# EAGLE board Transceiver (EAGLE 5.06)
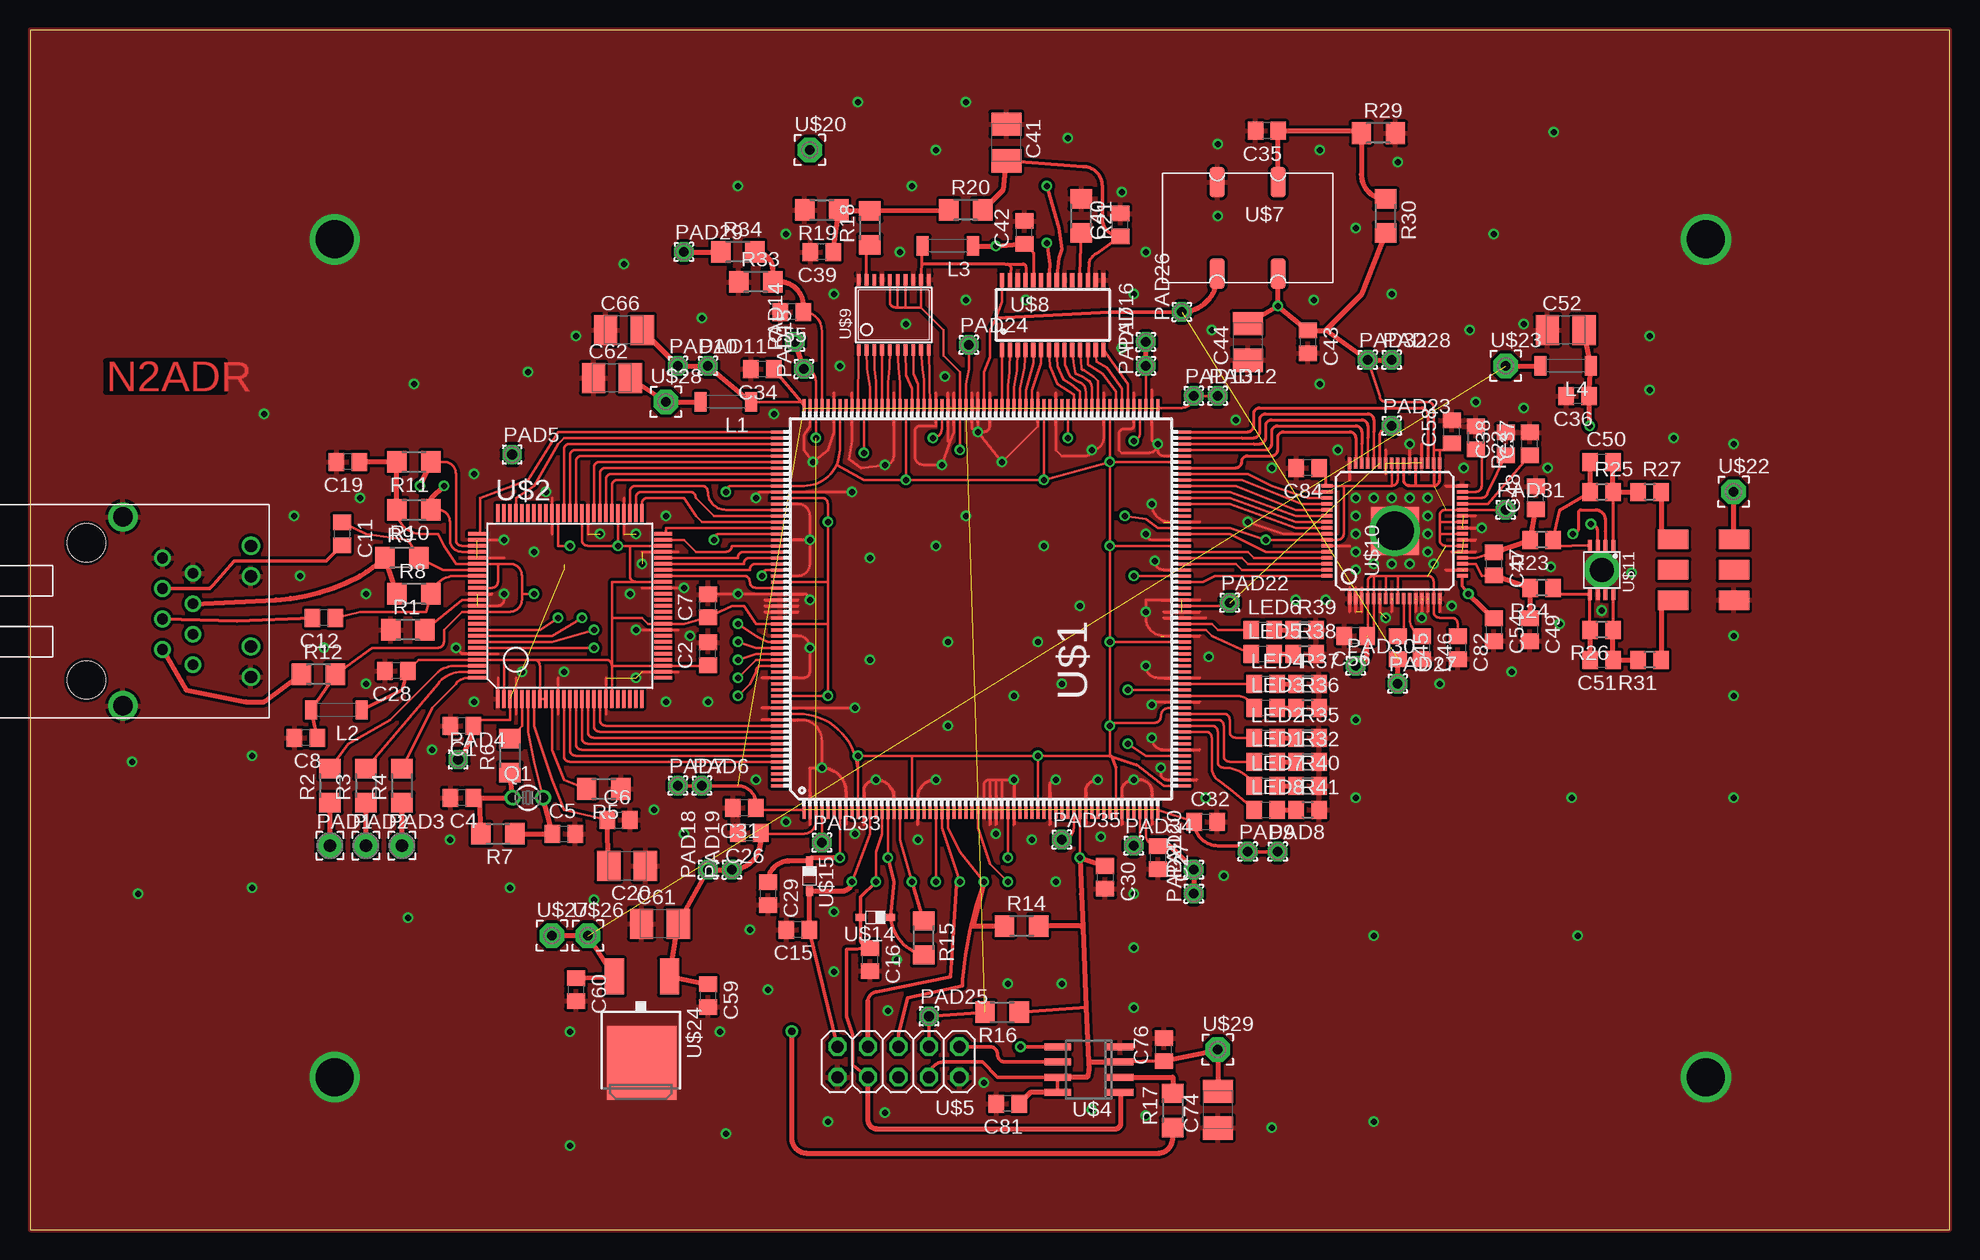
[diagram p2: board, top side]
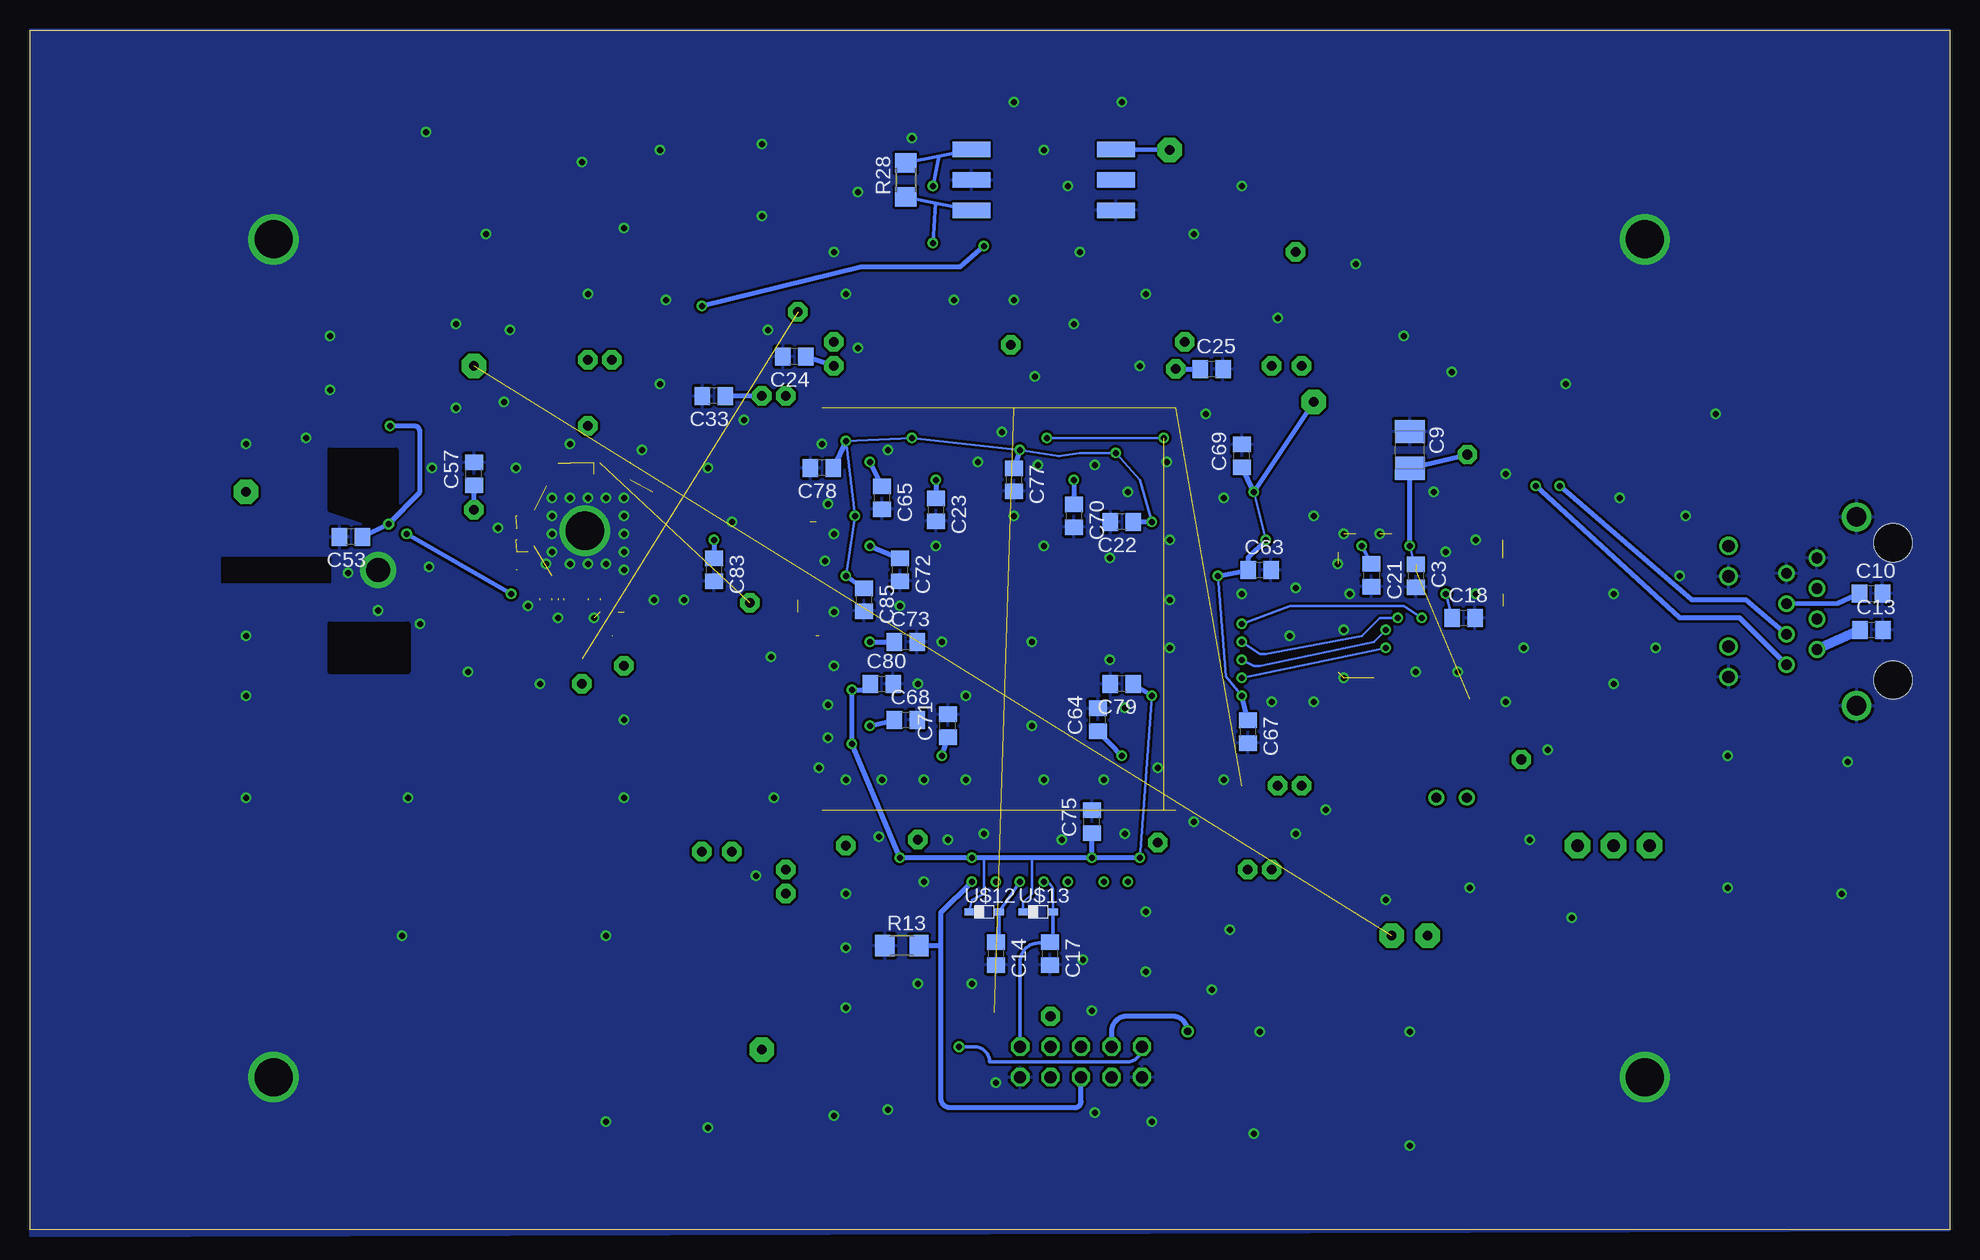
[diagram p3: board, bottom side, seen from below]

Size 160 x 100 mm. Coordinates in mm from the lower left corner, seen from the top.
Outline: 0,0 160,0 160,100 0,100 0,0
Copper layers (1*16): Top 0.035mm / dielectric 1.5mm / Bottom 0.035mm
Design rules "4pcb *": minimum track width 8mil, minimum drill 14mil, track to track 8mil, track to pad 8mil, pad to pad 6mil, via to via 8mil, smd to smd 0mil, copper to edge 0mil, drill to drill 8mil, minimum pad ring 10mil, minimum via ring 8mil, stop-mask expansion 4mil, vias tented up to drill 0mil, thermal gap 10mil
bRestrict: area 128.5,46.5 to 135,50.5; area 129.5,59 to 135,65; area 135,54 to 144,56

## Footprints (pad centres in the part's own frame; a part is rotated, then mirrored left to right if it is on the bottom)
MINI-CD637 = smd 1.651 x 2.54: P$1 -2.54,-2.54; P$2 0,-2.54; P$3 2.54,-2.54; P$4 2.54,2.54; P$5 0,2.54; P$6 -2.54,2.54
C0805 = smd 1.3 x 1.5: 1 -0.95,0; 2 0.95,0
B/3528-21R = smd 1.95 x 2.5: + 1.525,0; - -1.525,0
L4516C = smd 1 x 1.6: 1 -2.1,0; 2 2.1,0
2,15/1,0 = drill 1.016 pad 2.159 octagon: 1 0,0
1,6/0,8 = drill 0.813 pad 1.6 octagon: 1 0,0
TC26V = drill 0.813 round: 1 -1.27,0; 2 1.27,0
R1206 = smd 1.6 x 1.803: 1 -1.422,0; 2 1.422,0
R0805 = smd 1.3 x 1.5: 1 -0.95,0; 2 0.95,0
MINI-KK81 = smd 1.27 x 3.175: P$1 -2.54,6.032; P$2 0,6.032; P$3 2.54,6.032; P$4 2.54,-6.032; P$5 0,-6.032; P$6 -2.54,-6.032
PQFP240 = smd 1.5 x 0.25: 1 -16.75,14.75; 2 -16.75,14.25; 3 -16.75,13.75; 4 -16.75,13.25; 5 -16.75,12.75; 6 -16.75,12.25; 7 -16.75,11.75; 8 -16.75,11.25; 9 -16.75,10.75; 10 -16.75,10.25; 11 -16.75,9.75; 12 -16.75,9.25; 13 -16.75,8.75; 14 -16.75,8.25; 15 -16.75,7.75; 16 -16.75,7.25; 17 -16.75,6.75; 18 -16.75,6.25; 19 -16.75,5.75; 20 -16.75,5.25; 21 -16.75,4.75; 22 -16.75,4.25; 23 -16.75,3.75; 24 -16.75,3.25; 25 -16.75,2.75; 26 -16.75,2.25; 27 -16.75,1.75; 28 -16.75,1.25; 29 -16.75,0.75; 30 -16.75,0.25; 31 -16.75,-0.25; 32 -16.75,-0.75; 33 -16.75,-1.25; 34 -16.75,-1.75; 35 -16.75,-2.25; 36 -16.75,-2.75; 37 -16.75,-3.25; 38 -16.75,-3.75; 39 -16.75,-4.25; 40 -16.75,-4.75; 41 -16.75,-5.25; 42 -16.75,-5.75; 43 -16.75,-6.25; 44 -16.75,-6.75; 45 -16.75,-7.25; 46 -16.75,-7.75; 47 -16.75,-8.25; 48 -16.75,-8.75; 49 -16.75,-9.25; 50 -16.75,-9.75; 51 -16.75,-10.25; 52 -16.75,-10.75; 53 -16.75,-11.25; 54 -16.75,-11.75; 55 -16.75,-12.25; 56 -16.75,-12.75; 57 -16.75,-13.25; 58 -16.75,-13.75; 59 -16.75,-14.25; 60 -16.75,-14.75; 121 16.75,-14.75; 122 16.75,-14.25; 123 16.75,-13.75; 124 16.75,-13.25; 125 16.75,-12.75; 126 16.75,-12.25; 127 16.75,-11.75; 128 16.75,-11.25; 129 16.75,-10.75; 130 16.75,-10.25; 131 16.75,-9.75; 132 16.75,-9.25; 133 16.75,-8.75; 134 16.75,-8.25; 135 16.75,-7.75; 136 16.75,-7.25; 137 16.75,-6.75; 138 16.75,-6.25; 139 16.75,-5.75; 140 16.75,-5.25; 141 16.75,-4.75; 142 16.75,-4.25; 143 16.75,-3.75; 144 16.75,-3.25; 145 16.75,-2.75; 146 16.75,-2.25; 147 16.75,-1.75; 148 16.75,-1.25; 149 16.75,-0.75; 150 16.75,-0.25; 151 16.75,0.25; 152 16.75,0.75; 153 16.75,1.25; 154 16.75,1.75; 155 16.75,2.25; 156 16.75,2.75; 157 16.75,3.25; 158 16.75,3.75; 159 16.75,4.25; 160 16.75,4.75; 161 16.75,5.25; 162 16.75,5.75; 163 16.75,6.25; 164 16.75,6.75; 165 16.75,7.25; 166 16.75,7.75; 167 16.75,8.25; 168 16.75,8.75; 169 16.75,9.25; 170 16.75,9.75; 171 16.75,10.25; 172 16.75,10.75; 173 16.75,11.25; 174 16.75,11.75; 175 16.75,12.25; 176 16.75,12.75; 177 16.75,13.25; 178 16.75,13.75; 179 16.75,14.25; 180 16.75,14.75 | smd 0.25 x 1.5: 61 -14.75,-16.75; 62 -14.25,-16.75; 63 -13.75,-16.75; 64 -13.25,-16.75; 65 -12.75,-16.75; 66 -12.25,-16.75; 67 -11.75,-16.75; 68 -11.25,-16.75; 69 -10.75,-16.75; 70 -10.25,-16.75; 71 -9.75,-16.75; 72 -9.25,-16.75; 73 -8.75,-16.75; 74 -8.25,-16.75; 75 -7.75,-16.75; 76 -7.25,-16.75; 77 -6.75,-16.75; 78 -6.25,-16.75; 79 -5.75,-16.75; 80 -5.25,-16.75; 81 -4.75,-16.75; 82 -4.25,-16.75; 83 -3.75,-16.75; 84 -3.25,-16.75; 85 -2.75,-16.75; 86 -2.25,-16.75; 87 -1.75,-16.75; 88 -1.25,-16.75; 89 -0.75,-16.75; 90 -0.25,-16.75; 91 0.25,-16.75; 92 0.75,-16.75; 93 1.25,-16.75; 94 1.75,-16.75; 95 2.25,-16.75; 96 2.75,-16.75; 97 3.25,-16.75; 98 3.75,-16.75; 99 4.25,-16.75; 100 4.75,-16.75; 101 5.25,-16.75; 102 5.75,-16.75; 103 6.25,-16.75; 104 6.75,-16.75; 105 7.25,-16.75; 106 7.75,-16.75; 107 8.25,-16.75; 108 8.75,-16.75; 109 9.25,-16.75; 110 9.75,-16.75; 111 10.25,-16.75; 112 10.75,-16.75; 113 11.25,-16.75; 114 11.75,-16.75; 115 12.25,-16.75; 116 12.75,-16.75; 117 13.25,-16.75; 118 13.75,-16.75; 119 14.25,-16.75; 120 14.75,-16.75; 181 14.75,16.75; 182 14.25,16.75; 183 13.75,16.75; 184 13.25,16.75; 185 12.75,16.75; 186 12.25,16.75; 187 11.75,16.75; 188 11.25,16.75; 189 10.75,16.75; 190 10.25,16.75; 191 9.75,16.75; 192 9.25,16.75; 193 8.75,16.75; 194 8.25,16.75; 195 7.75,16.75; 196 7.25,16.75; 197 6.75,16.75; 198 6.25,16.75; 199 5.75,16.75; 200 5.25,16.75; 201 4.75,16.75; 202 4.25,16.75; 203 3.75,16.75; 204 3.25,16.75; 205 2.75,16.75; 206 2.25,16.75; 207 1.75,16.75; 208 1.25,16.75; 209 0.75,16.75; 210 0.25,16.75; 211 -0.25,16.75; 212 -0.75,16.75; 213 -1.25,16.75; 214 -1.75,16.75; 215 -2.25,16.75; 216 -2.75,16.75; 217 -3.25,16.75; 218 -3.75,16.75; 219 -4.25,16.75; 220 -4.75,16.75; 221 -5.25,16.75; 222 -5.75,16.75; 223 -6.25,16.75; 224 -6.75,16.75; 225 -7.25,16.75; 226 -7.75,16.75; 227 -8.25,16.75; 228 -8.75,16.75; 229 -9.25,16.75; 230 -9.75,16.75; 231 -10.25,16.75; 232 -10.75,16.75; 233 -11.25,16.75; 234 -11.75,16.75; 235 -12.25,16.75; 236 -12.75,16.75; 237 -13.25,16.75; 238 -13.75,16.75; 239 -14.25,16.75; 240 -14.75,16.75
TQFP100 = smd 0.27 x 1.5: 1 -6,-7.75; 2 -5.5,-7.75; 3 -5,-7.75; 4 -4.5,-7.75; 5 -4,-7.75; 6 -3.5,-7.75; 7 -3,-7.75; 8 -2.5,-7.75; 9 -2,-7.75; 10 -1.5,-7.75; 11 -1,-7.75; 12 -0.5,-7.75; 13 0,-7.75; 14 0.5,-7.75; 15 1,-7.75; 16 1.5,-7.75; 17 2,-7.75; 18 2.5,-7.75; 19 3,-7.75; 20 3.5,-7.75; 21 4,-7.75; 22 4.5,-7.75; 23 5,-7.75; 24 5.5,-7.75; 25 6,-7.75; 51 6,7.75; 52 5.5,7.75; 53 5,7.75; 54 4.5,7.75; 55 4,7.75; 56 3.5,7.75; 57 3,7.75; 58 2.5,7.75; 59 2,7.75; 60 1.5,7.75; 61 1,7.75; 62 0.5,7.75; 63 0,7.75; 64 -0.5,7.75; 65 -1,7.75; 66 -1.5,7.75; 67 -2,7.75; 68 -2.5,7.75; 69 -3,7.75; 70 -3.5,7.75; 71 -4,7.75; 72 -4.5,7.75; 73 -5,7.75; 74 -5.5,7.75; 75 -6,7.75 | smd 1.5 x 0.27: 26 7.75,-6; 27 7.75,-5.5; 28 7.75,-5; 29 7.75,-4.5; 30 7.75,-4; 31 7.75,-3.5; 32 7.75,-3; 33 7.75,-2.5; 34 7.75,-2; 35 7.75,-1.5; 36 7.75,-1; 37 7.75,-0.5; 38 7.75,0; 39 7.75,0.5; 40 7.75,1; 41 7.75,1.5; 42 7.75,2; 43 7.75,2.5; 44 7.75,3; 45 7.75,3.5; 46 7.75,4; 47 7.75,4.5; 48 7.75,5; 49 7.75,5.5; 50 7.75,6; 76 -7.75,6; 77 -7.75,5.5; 78 -7.75,5; 79 -7.75,4.5; 80 -7.75,4; 81 -7.75,3.5; 82 -7.75,3; 83 -7.75,2.5; 84 -7.75,2; 85 -7.75,1.5; 86 -7.75,1; 87 -7.75,0.5; 88 -7.75,0; 89 -7.75,-0.5; 90 -7.75,-1; 91 -7.75,-1.5; 92 -7.75,-2; 93 -7.75,-2.5; 94 -7.75,-3; 95 -7.75,-3.5; 96 -7.75,-4; 97 -7.75,-4.5; 98 -7.75,-5; 99 -7.75,-5.5; 100 -7.75,-6
MAGJACK2 = drill 1.016 round: D1+ 13.716,2.921; D1- 13.716,5.461; D2+ 13.716,-5.461; D2- 13.716,-2.921 | drill 0.889 round: GND 6.35,4.445; PIN7 8.89,3.175; RCT 8.89,0.635; RD+ 6.35,-0.635; RD- 6.35,1.905; TCT 6.35,-3.175; TD+ 8.89,-4.445; TD- 8.89,-1.905 | drill 1.626 round: P$1 3.048,7.874; P$2 3.048,-7.874 | hole 3.175: 0,5.715; 0,-5.715
SOIC-8 = smd 0.6 x 2.2: 1 -1.905,-2.6; 2 -0.635,-2.6; 3 0.635,-2.6; 4 1.905,-2.6; 5 1.905,2.6; 6 0.635,2.6; 7 -0.635,2.6; 8 -1.905,2.6
2X05 = drill 1.016 octagon: 1 -5.08,-1.27; 2 -5.08,1.27; 3 -2.54,-1.27; 4 -2.54,1.27; 5 0,-1.27; 6 0,1.27; 7 2.54,-1.27; 8 2.54,1.27; 9 5.08,-1.27; 10 5.08,1.27
CLOCKSMD2 = smd 1.27 x 2.54: P$1 -2.54,-3.81; P$2 2.54,-3.81; P$3 2.54,3.81; P$4 -2.54,3.81
TSSOP28 = smd 0.35 x 1.2: 1 -4.225,-2.9; 2 -3.575,-2.9; 3 -2.925,-2.9; 4 -2.275,-2.9; 5 -1.625,-2.9; 6 -0.975,-2.9; 7 -0.325,-2.9; 8 0.325,-2.9; 9 0.975,-2.9; 10 1.625,-2.9; 11 2.275,-2.9; 12 2.925,-2.9; 13 3.575,-2.9; 14 4.225,-2.9; 15 4.225,2.9; 16 3.575,2.9; 17 2.925,2.9; 18 2.275,2.9; 19 1.625,2.9; 20 0.975,2.9; 21 0.325,2.9; 22 -0.325,2.9; 23 -0.975,2.9; 24 -1.625,2.9; 25 -2.275,2.9; 26 -2.925,2.9; 27 -3.575,2.9; 28 -4.225,2.9
TSSOP20 = smd 0.305 x 0.991: 1 -2.925,-2.918; 2 -2.275,-2.918; 3 -1.625,-2.918; 4 -0.975,-2.918; 5 -0.325,-2.918; 6 0.325,-2.918; 7 0.975,-2.918; 8 1.625,-2.918; 9 2.275,-2.918; 10 2.925,-2.918; 11 2.925,2.918; 12 2.275,2.918; 13 1.625,2.918; 14 0.975,2.918; 15 0.325,2.918; 16 -0.325,2.918; 17 -0.975,2.918; 18 -1.625,2.918; 19 -2.275,2.918; 20 -2.925,2.918
LQFP64-PPAD = smd 0.9 x 0.3: 1 -5.65,3.75; 2 -5.65,3.25; 3 -5.65,2.75; 4 -5.65,2.25; 5 -5.65,1.75; 6 -5.65,1.25; 7 -5.65,0.75; 8 -5.65,0.25; 9 -5.65,-0.25; 10 -5.65,-0.75; 11 -5.65,-1.25; 12 -5.65,-1.75; 13 -5.65,-2.25; 14 -5.65,-2.75; 15 -5.65,-3.25; 16 -5.65,-3.75; 33 5.65,-3.75; 34 5.65,-3.25; 35 5.65,-2.75; 36 5.65,-2.25; 37 5.65,-1.75; 38 5.65,-1.25; 39 5.65,-0.75; 40 5.65,-0.25; 41 5.65,0.25; 42 5.65,0.75; 43 5.65,1.25; 44 5.65,1.75; 45 5.65,2.25; 46 5.65,2.75; 47 5.65,3.25; 48 5.65,3.75 | smd 0.3 x 0.9: 17 -3.75,-5.65; 18 -3.25,-5.65; 19 -2.75,-5.65; 20 -2.25,-5.65; 21 -1.75,-5.65; 22 -1.25,-5.65; 23 -0.75,-5.65; 24 -0.25,-5.65; 25 0.25,-5.65; 26 0.75,-5.65; 27 1.25,-5.65; 28 1.75,-5.65; 29 2.25,-5.65; 30 2.75,-5.65; 31 3.25,-5.65; 32 3.75,-5.65; 49 3.75,5.65; 50 3.25,5.65; 51 2.75,5.65; 52 2.25,5.65; 53 1.75,5.65; 54 1.25,5.65; 55 0.75,5.65; 56 0.25,5.65; 57 -0.25,5.65; 58 -0.75,5.65; 59 -1.25,5.65; 60 -1.75,5.65; 61 -2.25,5.65; 62 -2.75,5.65; 63 -3.25,5.65; 64 -3.75,5.65 | smd 4 x 4: 65 0,0
MSOP8-PPAD = smd 0.32 x 0.9: 1 -0.975,-2.05; 2 -0.325,-2.05; 3 0.325,-2.05; 4 0.975,-2.05; 5 0.975,2.05; 6 0.325,2.05; 7 -0.325,2.05; 8 -0.975,2.05 | smd 2.06 x 1.83: 9 0,0
SOD323R_INFINEON = smd 0.8 x 0.6: A 1.28,-0.03; C -1.22,-0.03
PAD100 = drill 0.8 pad 2.032 octagon: 1 0,0
DPAK = smd 1.6 x 3: 1 -2.3,-7.1; 3 2.3,-7.1 | smd 5.8 x 6.2: 2 0,0.1

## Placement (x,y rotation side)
ADT4-6T  4:1  [MINI-CD637]  139.5,55 90 top
C1  10n  [C0805]  36,42 180 top
C2  100n  [C0805]  56.5,48 90 top
C3  10n  [C0805]  44.5,54.5 270 bottom
C4  30p  [C0805]  36,36 180 top
C5  30p  [C0805]  44.5,33 0 top
C6  10n  [C0805]  49.06,34.15 0 top
C7  100n  [C0805]  56.5,52 90 top
C8  100n  [C0805]  23,41 180 top
C9  10u  [B/3528-21R]  45,65 270 bottom
C10  10n  [C0805]  6.54,53.03 0 bottom
C11  10n  [C0805]  26,58 270 top
C12  10n  [C0805]  24.5,51 180 top
C13  22n  [C0805]  6.5,50 0 bottom
C14  10p  [C0805]  79.5,23 270 bottom
C15  10p  [C0805]  64,25 180 top
C16  10p  [C0805]  70,22.5 270 top
C17  10p  [C0805]  75,23 270 bottom
C18  100n  [C0805]  40.5,51 0 bottom
C19  100n  [C0805]  26.5,64 180 top
C20  10u  [B/3528-21R]  49.77,30.31 180 top
C21  100n  [C0805]  48.19,54.54 270 bottom
C22  100n  [C0805]  69,59 180 bottom
C23  100n  [C0805]  84.5,60 270 bottom
C24  100n  [C0805]  96.29,72.78 180 bottom
C25  100n  [C0805]  61.5,71.75 0 bottom
C26  100n  [C0805]  59.96,33.07 180 top
C27  100n  [C0805]  94,31 270 top
C28  100n  [C0805]  30.54,46.58 180 top
C29  100n  [C0805]  61.5,28 270 top
C30  100n  [C0805]  89.61,29.37 270 top
C31  100n  [C0805]  59.54,35.16 180 top
C32  100n  [C0805]  98,34 0 top
C33  100n  [C0805]  103,69.5 180 bottom
C34  100n  [C0805]  61.04,71.71 180 top
C35  100n  [C0805]  103.1,91.6 180 top
C36  100n  [C0805]  129,69.5 180 top
C37  1u  [C0805]  125,65.5 90 top
C38  1u  [C0805]  123,65.5 90 top
C39  100n  [C0805]  66,81.5 180 top
C40  100n  [C0805]  90.88,83.75 90 top
C41  10u  [B/3528-21R]  81.38,90.62 270 top
C42  100n  [C0805]  82.88,83.12 90 top
C43  100n  [C0805]  106.5,74 270 top
C44  10u  [B/3528-21R]  101.5,74 90 top
C45  10n  [C0805]  114,48.5 270 top
C46  10n  [C0805]  116,48.5 270 top
C47  15p  [C0805]  122,55.5 270 top
C48  15p  [C0805]  125.5,61 90 top
C49  15p  [C0805]  125,50 270 top
C50  8p  [C0805]  131,64 0 top
C51  8p  [C0805]  131,47.5 180 top
C52  10u  [B/3528-21R]  128,75 0 top
C53  100n  [C0805]  133.25,57.75 180 bottom
C54  100n  [C0805]  122,50 270 top
C55  100n  [C0805]  63.5,76.5 180 top
C56  100n  [C0805]  110.5,49.5 180 top
C57  100n  [C0805]  123,63 90 bottom
C58  100n  [C0805]  118.5,66.5 90 top
C59  1u  [C0805]  56.5,19.5 270 top
C60  1u  [C0805]  45.5,20 270 top
C61  10u  [B/3528-21R]  52.5,25.5 0 top
C62  10u  [B/3528-21R]  48.5,71 0 top
C63  100n  [C0805]  57.5,55 0 bottom
C64  100n  [C0805]  71,42.5 90 bottom
C65  100n  [C0805]  89,61 270 bottom
C66  10u  [B/3528-21R]  49.5,75 0 top
C67  100n  [C0805]  58.5,41.5 270 bottom
C68  100n  [C0805]  87,42.5 0 bottom
C69  100n  [C0805]  59,64.5 90 bottom
C70  100n  [C0805]  73,59.5 270 bottom
C71  100n  [C0805]  83.5,42 90 bottom
C72  100n  [C0805]  87.5,55 270 bottom
C73  100n  [C0805]  87,49 0 bottom
C74  10u  [B/3528-21R]  99,10 90 top
C75  100n  [C0805]  71.5,34 90 bottom
C76  100n  [C0805]  94.5,15 90 top
C77  100n  [C0805]  78,62.5 270 bottom
C78  100n  [C0805]  94,63.5 180 bottom
C79  100n  [C0805]  69,45.5 180 bottom
C80  100n  [C0805]  89,45.5 0 bottom
C81  100n  [C0805]  81.5,10.5 180 top
C82  100n  [C0805]  119,48.5 270 top
C83  100n  [C0805]  103,55 270 bottom
C84  100n  [C0805]  106.5,63.5 180 top
C85  100n  [C0805]  90.5,52.5 270 bottom
L1  [L4516C]  58,69 180 top
L2  [L4516C]  25.54,43.31 180 top
L3  [L4516C]  76.5,82 180 top
L4  [L4516C]  128,72 180 top
LED1  [C0805]  103,39 0 top
LED2  [C0805]  103,41 0 top
LED3  [C0805]  103,43.5 0 top
LED4  [C0805]  103,45.5 0 top
LED5  [C0805]  102.75,48 0 top
LED6  [C0805]  102.75,50 0 top
LED7  [C0805]  103,37 0 top
LED8  [C0805]  103,35 0 top
PAD1  [2,15/1,0]  25,32 0 top
PAD2  [2,15/1,0]  28,32 0 top
PAD3  [2,15/1,0]  31,32 0 top
PAD4  [1,6/0,8]  35.69,39.19 0 top
PAD5  [1,6/0,8]  40.19,64.61 0 top
PAD6  [1,6/0,8]  56,37 0 top
PAD7  [1,6/0,8]  54,37 0 top
PAD8  [1,6/0,8]  104,31.5 0 top
PAD9  [1,6/0,8]  101.5,31.5 0 top
PAD10  [1,6/0,8]  54,72 0 top
PAD11  [1,6/0,8]  56.5,72 0 top
PAD12  [1,6/0,8]  99,69.5 0 top
PAD13  [1,6/0,8]  97,69.5 0 top
PAD14  [1,6/0,8]  63.75,74 90 top
PAD15  [1,6/0,8]  64.5,71.75 90 top
PAD16  [1,6/0,8]  93,74 90 top
PAD17  [1,6/0,8]  93,72 90 top
PAD18  [1,6/0,8]  56.5,30 90 top
PAD19  [1,6/0,8]  58.5,30 90 top
PAD20  [1,6/0,8]  97,30 90 top
PAD21  [1,6/0,8]  97,28 90 top
PAD22  [1,6/0,8]  100,52.25 0 top
PAD23  [1,6/0,8]  113.5,67 0 top
PAD24  [1,6/0,8]  78.25,73.75 0 top
PAD25  [1,6/0,8]  74.93,17.78 0 top
PAD26  [1,6/0,8]  96,76.5 90 top
PAD27  [1,6/0,8]  114,45.5 0 top
PAD28  [1,6/0,8]  113.5,72.5 0 top
PAD29  [1,6/0,8]  54.5,81.5 0 top
PAD30  [1,6/0,8]  110.5,47 0 top
PAD31  [1,6/0,8]  123,60 0 top
PAD32  [1,6/0,8]  111.5,72.5 0 top
PAD33  [1,6/0,8]  66,32.25 0 top
PAD34  [1,6/0,8]  92,32 0 top
PAD35  [1,6/0,8]  86,32.5 0 top
Q1  25 MHz  [TC26V]  41.5,36 0 top
R1  12.4k  [R1206]  31.5,50 0 top
R2  220  [R1206]  25,37 90 top
R3  220  [R1206]  28,37 90 top
R4  220  [R1206]  31,37 90 top
R5  12.0k  [R1206]  47.83,36.73 180 top
R6  10  [R1206]  40,39.5 90 top
R7  1 Meg  [R1206]  39,33 180 top
R8  49.9  [R1206]  32,53 0 top
R9  49.9  [R1206]  31,56 0 top
R10  49.9  [R1206]  32,60 180 top
R11  49.9  [R1206]  32,64 180 top
R12  10  [R1206]  24.04,46.28 0 top
R13  10k  [R1206]  87.32,23.65 0 bottom
R14  10k  [R1206]  82.66,25.3 0 top
R15  10k  [R1206]  74.49,24.31 270 top
R16  10k  [R1206]  81.03,18.12 180 top
R17  25  [R1206]  95.25,9.93 90 top
R18  1800  [R1206]  70,83.5 90 top
R19  1500  [R1206]  66,85 180 top
R20  1000  [R1206]  78,85 0 top
R21  2k  [R1206]  87.62,84.5 270 top
R22  56.2k  [R0805]  120.5,66 270 top
R23  49.9  [R0805]  126,57.5 180 top
R24  49.9  [R0805]  126,53.5 180 top
R25  300  [R0805]  131,61.5 0 top
R26  300  [R0805]  131,50 180 top
R27  100  [R0805]  135,61.5 0 top
R28  180  [R1206]  87,87.5 90 bottom
R29  10k  [R1206]  112.4,91.4 0 top
R30  10k  [R1206]  113,84.5 270 top
R31  100  [R0805]  135,47.5 180 top
R32  220  [R0805]  106.5,39 0 top
R33  2000  [R1206]  60.5,79 0 top
R34  1000  [R1206]  59,81.5 0 top
R35  220  [R0805]  106.5,41 0 top
R36  220  [R0805]  106.5,43.5 0 top
R37  220  [R0805]  106.5,45.5 0 top
R38  220  [R0805]  106.25,48 0 top
R39  220  [R0805]  106.25,50 0 top
R40  220  [R0805]  106.5,37 0 top
R41  220  [R0805]  106.5,35 0 top
T1-1T-KK81  1:1  [MINI-KK81]  75.5,87.5 90 bottom
U$1  EP3C25  [PQFP240]  79.25,51.75 90 top
U$2  LAN9115  [TQFP100]  45,52 0 top
U$3  [MAGJACK2]  4.7,51.53 0 top
U$4  EPCS4  [SOIC-8]  88.27,13.34 90 top
U$5  FPGA-ISP  [2X05]  72.39,13.97 180 top
U$7  CLOCKCVHD  [CLOCKSMD2]  101.5,83.5 180 top
U$8  AD9744  [TSSOP28]  85.25,76.25 0 top
U$9  AD7801  [TSSOP20]  72,76.25 0 top
U$10  ADS5500  [LQFP64-PPAD]  113.75,58.25 90 top
U$11  LTC6405  [MSOP8-PPAD]  131,55 180 top
U$12  DIODE-SH  [SOD323R_INFINEON]  80.5,26.5 0 bottom
U$13  DIODE-SH  [SOD323R_INFINEON]  76,26.5 0 bottom
U$14  DIODE-SH  [SOD323R_INFINEON]  70.5,26 180 top
U$15  DIODE-SH  [SOD323R_INFINEON]  65,29.5 270 top
U$20  PAD1TH86  [PAD100]  65,90 0 top
U$22  PAD1TH86  [PAD100]  142,61.5 0 top
U$23  PAD1TH86  [PAD100]  123,72 0 top
U$24  VREG3DPAK  [DPAK]  51,14 180 top
U$26  PAD1TH86  [PAD100]  46.5,24.5 0 top
U$27  PAD1TH86  [PAD100]  43.5,24.5 0 top
U$28  PAD1TH86  [PAD100]  53,69 0 top
U$29  PAD1TH86  [PAD100]  99,15 0 top

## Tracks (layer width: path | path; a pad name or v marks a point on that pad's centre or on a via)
+1.2V  (via drill 0.5)
  Top 0.22: U$1.198 57.5,58 arc90 v57,57.5 | U$1.204 61.5,55 arc90 v61,54.5 | U$1.220 61,47 arc90 60.5,46.5 60,45.5 v59,44.5 | U$1.228 64,43 arc-90 69,38 | 69,38 U$1.10 | 90.5,38.5 U$1.53 | v84,39.5 U$1.40 | 73.5,39.5 v69,39.5 69,38 | v84,39.5 73.5,39.5 | 73.5,39.5 U$1.19 | 67.5,65 arc-90 64.5,62 U$1.190 58.5,62 arc90 v58,61.5 | 67.5,65 U$1.174 | v90,64 U$1.129 | v90,64 U$1.115 | v84.5,62.5 U$1.140 | v73,62.5 v84.5,62.5 | v73,62.5 U$1.163 | v84.5,62.5 v90,64 | v90,64 v90,57 | v90,57 v90,49 | 90,42.25 v90,42 90,39.5 v84,39.5 | v90,49 90,42.25 | v90,49 U$1.85 | v90,57 U$1.101 | U$1.61 94.5,37 92.25,38.75 | v73,62.5 69.5,62.5 67.25,63.75 67.5,65 | U$1.74 95,43.5 arc90 94.25,42.75 arc-90 93.75,42.25 90,42.25
  Top 0.25: 90,39.5 90.15,39.45 | 90.15,39.45 92.25,38.75 | 90.15,39.45 90.5,38.5
  Top 0.406: C62.+ U$28.1 L1.2
  Bottom 0.22: v57,57.5 v58,61.5 | v61,54.5 60.3,46.1 v59,44.5
  Bottom 0.406: U$28.1 v58,61.5 C69.1 | C67.1 v59,44.5 | v73,62.5 C70.1 | v69,39.5 C64.1 | v84,39.5 C71.1 | v90,42 C68.1 | v90,49 C73.1 | v90,57 C72.1 | v90,64 C65.1 | v84.5,62.5 C23.1 | v61,54.5 C63.1 58.45,56.05 v57,57.5
+2.5V  (via drill 0.5)  (3 unrouted)
  Top 0.22: U$1.58 93,32.95 arc90 C27.1 | U$1.3 65.5,34 arc-90 64.5,33 60.98,33 arc-90 C26.1 | v65.5,66 U$1.178 65.5,70.75 arc90 PAD15.1 | U$1.157 76,66.75 arc-90 v75.25,66 | U$1.123 PAD17.1
  Top 0.406: C27.1 95.05,31.95 PAD20.1 PAD21.1 | C26.1 60.91,32.41 arc-90 PAD19.1 PAD18.1 C61.+ U$24.1 C59.1 | PAD15.1 PAD14.1 | PAD17.1 PAD16.1
  Bottom 0.22: v65.5,66 v75.25,66
  Bottom 0.406: PAD17.1 C24.1 | PAD15.1 C25.1
+3.3V  (via drill 0.5, 0.5 pad 0.5)
  Top 0.22: C2.1 56.5,47 U$2.28 48.5,47 | 39.5,47.5 U$2.97 32.41,47.5 C28.1 | 39.5,47.5 42,47.5 | 42,47.5 arc-90 42.5,47 U$2.8 U$2.9 | 39.5,47.5 U$2.2 | 48.5,47 U$2.20 | 48.5,47 arc90 48,47.5 42,47.5 | U$2.61 46,57.5 arc90 46.5,57 48.5,57 | 48.5,57 arc90 49,57.5 U$2.55 | 50,57 v49,57 48.5,57 | 50,57 U$2.48 | 50.5,54 U$2.42 | 50.5,54 arc-90 50,54.5 50,57 | 66,44.5 U$1.225 | 66,44.5 arc90 66.5,45 66.5,50.5 | 66.5,50.5 U$1.213 60.5,50.5 59.5,52 58.5,52 C7.1 54.5,50.5 U$2.35 51.5,50.5 51,51 48.5,51 | U$1.192 66,61 arc-90 66.5,60.5 v66.5,59 66.5,54 | 66.5,50.5 66.5,54 | 66.5,54 U$1.206 | v71.5,31 U$1.15 | v87.5,31 U$1.47 | v81.5,31 U$1.35 | v67.5,31 U$1.7 | v69.5,64.75 U$1.170 | U$1.124 92.5,66.5 arc-90 v92,65.75 | v77.5,65 U$1.154 77.5,71.5 76.12,72.88 76.12,75 74.25,76.88 | v86.5,66 U$1.136 | 66,44.5 v66.5,44.5 | 48.5,47 48.5,51 | 48.5,51 48.5,54 50.5,54 | v92,54.5 U$1.96 | v91.25,59.5 93,59.25 94,58.5 U$1.104 100,58.5 v103,57.5 U$10.58 109,57.5 arc90 109.5,58 109.5,62 | 74.25,76.88 74.25,79.14 U$9.12 | U$9.16 71.67,77.33 arc90 72.12,76.88 72.25,76.88 | 74.25,76.88 73,76.88 | 73,76.88 72.25,76.88 | U$9.15 72.33,76.95 arc-90 72.25,76.88 | U$9.14 72.97,76.9 arc90 73,76.88 | 109,62 U$10.49 109.5,62 | U$10.40 114,62.5 arc-90 113.5,62 | 109.5,62 113.5,62 | 113.5,62 U$10.41 | v91.5,40.5 93,39.5 U$1.66 | v91.5,45 U$1.77
  Top 0.25: U$9.12 74.33,80.51 | 74.33,80.51 L3.2 | U$8.27 81.75,80.25 81.5,80.5 81.25,80.5 | 81.25,80.5 81.24,80.51 74.33,80.51 | U$8.25 83,79.17 83,80.25 arc90 82.75,80.5 81.25,80.5 | U$10.49 arc-90 108,62.1 108,63.5 arc180 C84.1
  Top 0.3: v71.5,31 72,29 U$14.C arc72 R15.2 | U$4.8 U$4.7 80.64,12.7 79.38,13.97 76.2,13.97 arc90 U$5.4 | 88.04,18.5 R16.1 | L2.1 31,45 C28.1
  Top 0.305: U$4.3 C76.1
  Top 0.406: C29.1 arc-90 63.27,30.72 U$15.C arc-90 65.25,31 v67.5,31 | 88.24,13.96 88.27,13.34 88.14,12.7 U$4.7 | 88.24,13.96 88.04,18.5 87.75,25.16 | 87.75,25.16 87.63,27.95 v87.5,31 C30.1 | 88.24,13.96 U$4.3 | R14.2 87.61,25.3 87.75,25.16 | C76.1 U$29.1 C74.+ | C81.1 83.38,11.43 U$4.8
  Bottom 0.22: U$13.C 77.22,27.28 76.5,28 76.5,31 | U$12.C 81.5,27.5 80.5,28 80.5,31 | v66.5,59 67.5,62.5 v69.5,64.75 72.5,64.75 74.25,64.5 v77.5,65 v86.5,66 v92,65.75 v91.25,59.5 v92,54.5 | v66.5,44.5 v67.5,31
  Bottom 0.3: v49,57 C21.1
  Bottom 0.406: v67.5,31 v71.5,31 | v71.5,31 76.5,31 80.5,31 v81.5,31 v87.5,31 v91.5,40.5 v91.5,45 90.45,45 C80.1 | v66.5,59 C22.1 | v71.5,31 C75.1 | v66.5,44.5 C79.1 | v77.5,65 C77.1 | v92,65.75 C78.1 | v92,54.5 C85.1 | v103,57.5 C83.1
+5.0V  (1 unrouted)
  Top 0.406: U$23.1 L4.2 | C60.1 U$24.3 U$26.1 U$27.1
AVCC  (via drill 0.5)  (3 unrouted)
  Top 0.22: U$10.4 111.5,54 arc-90 112,54.5 | 112,54.5 113,54.5 | 113,54.5 113.5,54.5 | 112,54.5 U$10.5 112,49.5 111.5,49.5 111.5,52.5 | 113,54.5 U$10.7 | 117.5,58 117.5,57.5 arc90 118,57 U$10.22 | 117.5,58 117.5,59 | 117.5,59 117.5,59.5 arc-90 118,60 U$10.28 PAD31.1 | 117.5,59 U$10.26 | 117.5,58 U$10.24 | 117,65 117,68.5 arc90 116.5,69 113,69 arc-90 112.5,69.5 PAD32.1 | 117,65 U$10.34 | 113,54.5 114,54.5 | 114,54.5 116.5,54.5 arc-90 117,54 U$10.15 117,51.5 arc90 117.5,51 118.5,51 arc-90 119,50.5 C82.1 | 114,54.5 U$10.9 | 117,65 117.5,65 | 117.5,65 117.5,64 | 117.5,65 118.5,65 C58.1
  Top 0.25: U$8.24 83.62,81.42 C42.1 | U$10.39 114.5,62.5 arc90 115,62 115.5,62 | 117,62 115.5,62 | 117,62 arc90 117.5,62.5 U$10.33 | 115.5,62 U$10.37 | U$10.34 117,62
  Top 0.406: L3.1 v80.5,82 C42.1 | 104.04,77 v104,77 C44.+ | 104.04,77 U$7.P$4 | 104.04,77 C43.1 107.95,74.95 108,75 | 108,75 111,78 R30.2 | 108,75 PAD32.1 PAD28.1 | C56.1 111.45,47.95 arc-90 PAD30.1
  Bottom 0.406: PAD31.1 C57.1 | v104,77 90.75,80.25 82.5,80.25 v80.5,82
GND  (via drill 0.5, 0.5 pad 0.22, 0.5 pad 0.5, 0.5 pad 0.6, 2 pad 0.81, 3.17, 3.17 pad 0.81)  (30 unrouted)
  Top 0.22: U$2.88 39,52 arc90 39.5,52.5 v39.5,53 | U$2.77 v39.5,57.5 | U$2.80 39.5,56 | U$2.96 39,48 | U$2.1 39,46 | 40.5,46 U$2.4 40.5,43 | 44,46 U$2.11 44,43 | 48,46 U$2.19 48,43 | 54,50 U$2.34 51,50 | 54,46.5 U$2.27 51,46.5 | 54,53.5 U$2.41 51,53.5 | 54,56.5 U$2.47 51,56.5 | 49.5,61 U$2.54 49.5,58 | 46.5,60 U$2.60 46.5,58 | 43.5,61 U$2.66 43.5,58 | U$1.208 56.55,53 C7.2 | 64,60.5 arc-90 65,59.5 v65,57.5 65,55.5 arc-90 64,54.5 U$1.205 | 64.5,53 arc-90 v65,52.5 | 64,49.5 arc-90 v65,48.5 65,46.5 arc-90 64.5,46 64,46 U$1.222 | v68.5,61.5 U$1.191 61,61.5 arc90 v60.5,61 | U$1.122 93.5,67 93.5,66 arc90 v94,65.5 | U$1.116 94.5,64.5 arc-90 94,65 v94,65.5 | U$1.105 95,59 arc-90 v93.5,60.5 | U$1.97 94.5,55 arc-90 v93.75,55.75 | U$1.92 94.25,52.5 93,52.5 v93,51.5 93,51 arc90 94.5,49.5 U$1.86 | v93,47 arc90 94,46 94.5,46 U$1.79 | U$1.75 94.5,44 93.75,44 arc90 v93.5,43.75 | U$1.62 94.75,37.5 arc-90 94.25,38 v94.25,38.5 | U$1.67 94.5,40 arc-90 v93.5,41 | U$1.102 93.5,57.5 arc-90 v93,58 | U$1.130 89.5,67 89.5,66 arc-90 v88.5,65 arc-90 88,64.5 86,64.5 85.5,65 85.5,67 U$1.138 | v79,66.5 79,67.25 U$1.151 | v79,66.5 v81,64 84,67 84,67.25 U$1.141 | U$1.152 78.5,67.25 78.5,67 arc90 v79,66.5 | U$1.149 80,67 arc-90 79.5,66.5 v79,66.5 | U$1.125 92,67.25 92,67 arc-90 91.75,66.75 91.25,66.75 arc90 90.75,66.25 90.75,65 91,64.75 93.25,64.75 arc90 v94,65.5 | U$1.155 77,67 77,66.5 76.7,65.68 | 76.7,65.68 v76,63.75 74.5,63.75 arc-90 73.75,64.5 73.75,66.5 arc-90 74.25,67 75.5,67 75.5,67.25 U$1.158 | U$1.156 76.5,67 76.5,65.75 76.7,65.68 | U$1.165 72,67 72,64.5 arc-90 v71.25,63.75 69.25,63.5 68.25,64.25 68.5,65.75 68.5,67 U$1.172 | U$1.175 67,67.25 67,66.5 66.5,65 v65.25,64 64.5,65 64.5,66.25 65,67 U$1.179
  Top 0.22: U$1.227 v68.75,43.5 | U$1.229 64.25,42.5 arc-90 66,40.75 v66,38.5 | U$1.31 79.5,37 arc-90 80,37.5 | 80.5,37.5 80,37.5 | 81,37.5 80.5,37.5 | 81,37.5 v82,37.5 | 80,37.5 80,36.25 U$1.32 | 80.5,37.5 80.5,36.25 U$1.33 | U$1.34 81,37.5 | U$10.57 104.5,58 v101.5,59 | U$10.59 110,57
  Top 0.25: 64,60.5 U$1.193 | v65,57.5 U$1.199 | U$1.208 64.5,53 | 64,49.5 U$1.215 | 64,46 61,46 | 61,43.5 U$1.227 64,43.5 | 61,42.5 U$1.229 64,42.5 | U$1.2 65,36.5 | 65,36.5 65,38.5 v66,38.5 arc-90 68,36.5 | 68,36.5 U$1.8 | U$1.11 69.5,36.5 | 69.5,36.5 arc-90 v70.5,37.5 arc-90 72,36 U$1.16 | U$1.20 74,36 arc-90 v75.5,37.5 | 82,36.5 U$1.36 | v82,37.5 82,36.5 | U$1.42 85,36.5 | 85,36.5 85,37 arc-90 v85.5,37.5 | U$1.48 88,36.5 | 88,36.5 arc-90 v89,37.5 | U$1.54 91,36.25 | 91,36.25 91,36.5 arc-90 v92,37.5 92.5,37.5 arc-90 93.5,36.5 93.5,36.25 | 93.5,36.25 U$1.59 | 65,36.5 65,33.75 | 68,36.5 68,33.75 | 69.5,36.5 69.5,33.75 | 72,34.5 72,36.5 | 74,33.75 74,36.25 | 82,36.5 82,33.75 | 85,36.5 85,33.75 | 88,36.5 88,33.75 | 91,36.25 91,33.75 | 93.5,36.25 93.5,33.75 | U$2.96 36,48 v35.5,48.5 | 61.25,52.5 64,52.5 | 61.25,52 64,52 | 61.25,51.5 64,51.5 | 67,67.25 67,69.75 | 68.5,67 68.5,69.75 | 72,67 72,69.75 | 75.5,67.25 75.5,69.75 | 76.5,67 76.5,69.75 | 77,67 77,69.75 | 78.5,67.25 78.5,69.75 | 79,67.25 79,69.75 | 80,67 80,69.75 | 84,67.25 84,69.75 | 85.5,67 85.5,69.75 | 89.5,67 89.5,69.75 | 92,67.25 92,69.75 | 93.5,67 93.5,70 | 94.5,59 97.5,59 | 94.5,55 96.5,55 | 94.25,52.5 97.5,52.5 | 94.25,49.5 97.5,49.5 | 94.5,46 97.5,46 | 94.5,44 97.5,44 | 94.25,40 97.5,40 | 94.75,37.5 97.25,37.5 | 80,36.25 80,33.75 | 80.5,36.25 80.5,33.75 | 113,63 113,65 | 110,62.5 110,64 | 94.5,51.5 97.5,51.5 | 94.5,51 98,51 | U$10.50 107,61.5 | 115,65 v115,65.5 U$10.38 | U$10.36 116,65.5 | 118,55 119.5,55 | 119.5,58.5 120.5,58.5 | 119.5,57.5 120.5,57.5 | 118,62 119.5,62 | 115.5,52.5 115.5,51.5 | 116,52.5 116,51.5 | 116.5,52.5 116.5,51.5 | 117.5,52.5 117.5,51.5 | 110,51.5 110,53.5 | 110.5,51.5 110.5,53.5 | 111,51.5 111,53.5 | 112.5,52.5 112.5,51.5 | 113.5,52.5 113.5,51.5
  Top 0.25: 118.5,56.5 120.5,56.5 | 120.5,59.5 119.5,59.5 | U$11.6 130.7,54.3
  Top 0.254: U$2.86 38.5,53
  other vias: 59,53 81.5,20.5 63,34 67,21.5 67,26.5 80.5,33 41,46.5 44.5,46.5 50.5,46 53,44 56.5,44 50.5,50 55,49.5 28,53 51,55.5 50.5,58 50,53 75.5,57 76.25,71.12 108,52.5 110.5,42.5 117.5,45.5 98.25,47.75 109,65 103.5,63.5 131,51.6 131,55 113.75,58.25 119.5,63.5 25.4,12.7 25.4,82.55 139.7,82.55 139.7,12.7 76.5,49 116,51 113,51 110.5,61 110.5,59.5 110.5,58 110.5,56.5 110.5,55 112,61 113.5,61 115,61 116.5,61 116.5,59.5 116.5,58 116.5,56.5 117,55.5 115,55.5 113.5,55.5 112,55.5 118.5,52 27.5,61 24.5,48.5 18.5,39.5 18.5,28.5 19.5,68 32,70.5 41.5,71.5 31.5,26 40,28.5 37,44 37,63 42,56.5 45.5,74.5 56,76 53,59.5 62,68 49.5,80.5 59,87 63,83 67,78 67.5,72 70,56 70,47.5 78,59.5 84.5,57 87.5,52 78,77.5 72.5,81.5 75.5,90 69,94 78,94 86.5,91 91,86.5 93,81.5 92,78 91,73.5 99,90.5 107.5,90 110.5,83.5 107,77.5 114,89 113.5,78 107.5,70.5 98.5,75 100.5,67.5 120.5,69 124.5,68.5 124.5,75.5 120,75 122,83 127,91.5 135,74.5 135,70 137,66 142,65.5 142,49.5 142,44.5 110.5,36 128.5,36 142,36 123.5,46.5 105.5,52.5 98,36 99.5,29.5 92,28 84,49 86,45.5 82,44.5 85.5,29 92,23.5 76.5,42 74,32.5 83.5,32.5 60.5,37.5 60,25 61.5,20 54.5,33 52,35 47,27.5 35,32.5 8.5,39 9,28 45,16.5 57.5,16.5 66.5,9 93,9.5 86,20.5 92,18.5 58,8 45,7 103.5,8.5 129,24.5 112,24.5 112,9 73,75.5 83,77.5 73.5,87 99,84.5 121,58.5 126.75,55.25 126.5,63.5 133.5,54.75 127.5,50.5 22.5,54.5 22,59.5 28,45.5 33.5,40 68.75,33 89.25,32.75 71.25,9.75 88.5,10 71.5,18.25 79.5,12.25 72.25,22.5 47.5,58 43,61.5 54.5,53.5
  pour Top (isolate 0.25): 0,100 0,0 160,0 160,100
  pour Bottom: 0,0 0,100 160,100 160,-0.5
N$1  (via drill 0.5 pad 0.6)
  Top 0.22: 39,55.5 40,55.5 arc-90 41,54.5 41,53 | 39,55.5 U$2.81 35.5,55.5 34.5,57 34,58 32.58,58 arc-90 R10.2 | 41,53 41,52.5 arc-90 40,51.5 U$2.89 36,51.5 34.5,50 34.5,49 arc-90 34,48.5 28.5,48.5 R12.2 | U$2.85 38.5,53.5 arc90 39,54 39,55.5 | 41,53 v42,53
  Top 0.3: R12.2 L2.2 C8.1
  Top 0.406: R10.2 R11.2 C19.1
  Bottom 0.22: v42,53 C18.1
N$2  (via drill 0.5 pad 0.6)  (2 unrouted)
  Top 0.22: U$2.3 40,42.5 37,42.5 C1.1 | U$2.65 44,57 v45,57
  Top 0.406: PAD4.1 arc37 C1.1
  Bottom 0.22: 44.5,55 v45,57
  Bottom 0.406: v45,57 C9.+ PAD5.1
N$3
  Top 0.406: R6.1 Q1.1 37.5,36 | 37.5,36 C4.1 | R7.2 37.5,36
N$4
  Top 0.22: U$2.64 44.5,65 arc-90 45,65.5 U$1.183
N$5
  Top 0.22: U$2.5 41,42 R6.2
N$6
  Top 0.22: U$2.6 41.5,41.5 42,39 Q1.2
  Top 0.406: R7.1 C5.1 Q1.2
N$7
  Top 0.22: U$2.7 42,42 43.5,37.5 44.5,35 C6.1
  Top 0.406: C20.+ C6.1
N$8
  Top 0.22: U$2.10 43.5,40 44.5,37.5 R5.2
N$9
  Top 0.22: U$2.100 36.5,46 arc53 35.5,45.5 33.5,43.5 R4.2
N$10
  Top 0.22: U$2.99 36,46.5 arc53 34,45.5 R3.2
N$11
  Top 0.22: U$2.98 35.5,47 arc37 34,46.5 30,42.5 26.5,40.5 R2.2
N$12
  Top 0.22: U$2.87 36,52.5 R1.2
N$13
  Top 0.22: U$2.18 47.5,42.5 arc90 48,42 U$1.230
N$14
  Top 0.22: U$2.17 47,42 arc90 47.5,41.5 U$1.231
N$15
  Top 0.22: U$2.16 46.5,41.5 arc90 47,41 U$1.232
N$16
  Top 0.22: U$2.15 46,41 arc90 46.5,40.5 U$1.233
N$17
  Top 0.22: U$2.14 45.5,40.5 arc90 46,40 U$1.234
N$18
  Top 0.22: U$2.13 45,40 arc90 45.5,39.5 U$1.235
N$19
  Top 0.22: U$2.12 44.5,39.5 arc90 45,39 U$1.236
N$20
  Top 0.22: U$2.43 59.5,54.5 arc-90 60,54 arc90 60.5,53.5 U$1.207
N$21
  Top 0.22: U$2.44 60,55 arc-90 60.5,55.5 U$1.203
N$22
  Top 0.22: U$2.45 59.5,55.5 arc-90 60,56 U$1.202
N$23
  Top 0.22: U$2.46 59,56 arc-90 59.5,56.5 U$1.201
N$24
  Top 0.22: U$1.200 58.5,57 arc-90 58,56.5 55.5,56.5 54.5,57.5 U$2.49
N$25
  Top 0.22: U$1.197 53,58.5 53,58.25 arc-90 U$2.50
N$26
  Top 0.22: U$2.51 51,60.5 arc-90 51.5,61 54.5,61 55.5,59.5 56,59 U$1.196
N$27
  Top 0.22: U$2.52 50.5,61 arc-90 51,61.5 55,61.5 arc-90 55.5,61 57,59.5 U$1.195
N$28
  Top 0.22: U$2.53 50,61.5 arc-90 50.5,62 56,62 arc-90 56.5,61.5 arc90 58,60 U$1.194
N$29
  Top 0.22: U$2.56 48.5,62 arc-90 49,62.5 U$1.189
N$30
  Top 0.22: U$2.57 48,62.5 arc-90 48.5,63 U$1.188
N$31
  Top 0.22: U$2.58 47.5,63 arc-90 48,63.5 U$1.187
N$32
  Top 0.22: U$2.59 47,63.5 arc-90 47.5,64 U$1.186
N$33
  Top 0.22: U$2.62 45.5,64 arc-90 46,64.5 U$1.185
N$34
  Top 0.22: U$2.63 45,64.5 arc-90 45.5,65 U$1.184
N$35
  Top 0.25: U$9.19 69.72,81.78 arc90 69.5,82 69.92,82 arc90 R18.1
N$36
  Top 0.22: 40.5,59.5 U$2.72 40.5,61 42,62 44,65.5 44.5,66 U$1.182
N$37
  Top 0.22: U$2.76 37.5,58 37.5,61 41.5,62.5 44,66.5 U$1.181
N$38  (via drill 0.5 pad 0.6)
  Top 0.22: U$2.92 42.5,50 v44,51 | v59,50.5 60.5,49.5 arc14 61.5,49 U$1.216
  Bottom 0.22: v44,51 45.5,52 55,52 v59,50.5
N$39  (via drill 0.5 pad 0.6)
  Top 0.22: U$2.93 43.5,49.5 v46,51 | U$1.217 60.5,48.5 v59,49
  Bottom 0.22: v46,51 47.5,51 49,49.5 57,48 57.5,48 v59,49
N$40  (via drill 0.5 pad 0.6)
  Top 0.22: U$2.94 43.5,49 v47,50 | U$1.218 60.5,48 v59,47.5
  Bottom 0.22: v47,50 48,49 57.5,47 58,47 v59,47.5
N$41  (via drill 0.5 pad 0.6)
  Top 0.22: U$2.95 v47,48.5 | U$1.219 60.5,47.5 v59,46
  Bottom 0.22: v47,48.5 v59,46
N$42
  Top 0.406: R8.1 R9.1 arc-13 27.5,54.5 arc-26 20.5,52.5 U$3.RCT
  Bottom 0.406: U$3.RCT 9.3,52.2 C10.1
N$43
  Top 0.22: U$2.83 35.5,54.5 arc72 R8.2 33,51.5 27.5,51.5 C12.1
N$44
  Top 0.22: U$2.82 34.42,55 R9.2 31.5,57.5 28,58 C11.1
N$45
  Top 0.406: U$3.TCT 13,45 18,44 19.5,44 R12.1
  Bottom 0.813: C13.1 U$3.TCT
N$46  (via drill 0.5 pad 0.6)
  Top 0.22: U$2.78 36,57 arc-90 35.5,57.5 35.5,63 arc90 34.5,64 R11.1
  Top 0.406: v32.5,62 R11.1
  Bottom 0.406: U$3.TD- 17,52.5 21.5,52.5 v32.5,62
N$47  (via drill 0.5 pad 0.6)
  Top 0.22: U$2.79 36,56.5 arc-90 35,57.5 35,59 arc90 34,60 R10.1
  Top 0.406: R10.1 33.42,60.92 v34.5,62
  Bottom 0.406: v34.5,62 22.5,51 17.5,51 U$3.TD+
N$48
  Top 0.22: U$10.51 106.5,61 103.5,62 101.5,63 U$1.113
N$49  (1 unrouted)
  Top 0.22: U$1.150 79.5,71.5 80,72.75 80,75 80.5,76 81,77.38 U$8.28
  Top 0.3: 80.5,76 90,76.5 PAD26.1
  Top 0.406: PAD27.1 C45.2 | PAD26.1 arc94 U$7.P$3
N$50  (via drill 0.5 pad 0.5)
  Top 0.22: U$1.25 76.5,33.5 77.5,31.5 v79.5,29
  Top 0.3: U$5.5 72.39,16.26 73.15,19.3 77.72,20.32 77.73,20.8 arc-15 v79.5,29
  Top 0.406: 78.59,25.3 R14.1 | 78.59,25.3 78.49,25.4 | v79.5,29 78.59,25.3
N$51  (via drill 0.5 pad 0.5)
  Top 0.22: v75.5,29 U$1.23
  Top 0.3: U$5.1 80.01,15.24 arc-90 80.64,14.61 arc90 81.28,13.97 U$4.6
  Bottom 0.22: v75.5,29 arc90 74.72,28.22 U$13.A
  Bottom 0.3: U$13.A 74.72,23.95 C17.1 arc90 75.07,23.88 75.95,23.88 arc-90 77.47,22.35 U$5.1
N$52  (via drill 0.5 pad 0.5, 0.6)
  Top 0.22: U$1.24 76,33.5 v77.5,29
  Top 0.3: v77.5,29 arc90 77.22,28.72 76.72,21.07 70.61,19.81 arc90 69.85,19.05
  Top 0.406: U$5.7 69.85,19.05 | R17.1 95.25,7.62 arc-90 93.98,6.35 64.77,6.35 arc-90 63.5,7.62 v63.5,16.51
  Bottom 0.3: C14.1 79.22,23.95 U$12.A v77.5,29
  Bottom 0.406: U$5.7 69.85,16.51 arc90 68.58,17.78 64.77,17.78 arc90 v63.5,16.51
N$53  (via drill 0.5 pad 0.5)
  Top 0.22: U$1.14 71,33 70.5,31.5 v70.5,29
  Top 0.3: v70.5,29 69.22,27.72 U$14.A 69.22,24.23 arc90 C16.1 68.07,23.37 68.07,17.78 68.58,16.26 68.58,13.72 U$5.8
  Top 0.406: U$5.8 69.85,9.14 arc90 70.61,8.38 90.42,8.38 arc90 90.93,8.89 90.93,11.36 arc90 U$4.1
N$54  (via drill 0.5 pad 0.5)
  Top 0.22: U$1.12 70,33 v68.5,29
  Top 0.3: U$5.9 C15.1 | v82.55,15.24 U$4.5
  Top 0.406: C15.1 arc-90 64.97,25.48 U$15.A 67.72,28.22 arc90 v68.5,29
  Bottom 0.3: U$5.9 arc90 68.58,13.97 80.01,13.97 arc-90 81.28,15.24 v82.55,15.24
N$55
  Top 0.22: U$1.126 91.5,70.5 U$8.14
N$56  (1 unrouted)
  Top 0.22: U$1.153 78,70.5 78.25,71.75 PAD24.1
  Top 0.3: U$5.3 PAD25.1 R16.2
N$57  (via drill 0.5 pad 0.5)
  Top 0.22: U$1.17 72.5,32.5 v73.5,29
  Top 0.3: R15.1 v73.5,29
N$58
  Top 0.406: PAD1.1 R2.1
N$59
  Top 0.406: PAD2.1 R3.1
N$60
  Top 0.406: PAD3.1 R4.1
N$61  (via drill 0.5 pad 0.5)
  Top 0.22: v81.5,29 80,30.5 79,33.5 U$1.30
  Bottom 0.406: U$5.6 72.39,10.67 arc90 72.9,10.16 83.31,10.16 arc90 84.07,10.92 84.07,23.62 | 84.07,23.62 84.07,26.43 v81.5,29 | R13.2 84.1,23.65 84.07,23.62
N$62
  Top 0.22: U$1.127 91,70.12 89.75,71.88 88.88,72.38 U$8.13
N$63
  Top 0.22: U$1.128 90.5,69.88 89.38,71.38 88.38,72 arc-90 88.17,72.2 U$8.12
N$64
  Top 0.3: U$3.RD- 14.94,53.44 arc90 15,53.5 15.25,53.75 17,55.75 24.7,55.75 C11.2
N$65
  Top 0.3: U$3.RD+ 17.25,50.75 C12.2
N$66
  Top 0.22: U$8.11 87.62,71.88 arc90 87.88,71.62 88.62,71.12 89,70.75 U$1.131
N$67
  Top 0.22: U$1.132 88.5,70.25 arc53 88.25,70.75 arc16 87.12,71.38 arc-2 U$8.10
N$68
  Top 0.22: U$1.133 88,69.88 arc67 87.5,70.62 arc-26 86.62,71.25 86.25,72.12 U$8.9
N$69
  Top 0.22: U$1.134 87.5,69.88 86.75,70.5 86.12,70.88 85.62,72 U$8.8
N$70
  Top 0.22: U$1.135 87,69.62 85.62,70.5 85,72 U$8.7
N$71
  Top 0.22: U$1.142 83.5,70 84.25,72.25 U$8.6
N$72
  Top 0.22: U$1.143 83,70 83.62,72.25 U$8.5
N$73
  Top 0.22: U$1.144 82.5,70.12 82.88,71.88 U$8.4
N$74
  Top 0.22: U$1.145 82,70.25 82.25,71.62 U$8.3
N$75
  Top 0.22: U$1.146 81.5,70.38 81.62,71.5 U$8.2
N$76
  Top 0.22: U$1.147 81,71.25 U$8.1
N$77
  Top 0.22: U$1.171 U$9.1
N$78
  Top 0.22: U$1.169 70,70.25 69.75,71.75 U$9.2
N$79
  Top 0.22: U$1.168 70.5,70.75 70.38,71.75 U$9.3
N$80
  Top 0.22: U$1.167 U$9.4
N$81
  Top 0.22: U$1.159 U$9.10
N$82
  Top 0.22: U$1.160 74.5,70.88 74.38,71.75 U$9.9
N$83
  Top 0.22: U$1.161 74,70.5 73.62,71.38 U$9.8
N$84
  Top 0.22: U$1.162 73.5,70.12 73,71.25 U$9.7
N$85
  Top 0.22: U$1.164 72.5,70.62 72.38,71.88 U$9.6
N$86
  Top 0.22: U$1.166 71.5,70.62 71.62,71.88 U$9.5
N$87
  Top 0.406: U$4.2 95.25,12.7 R17.2
N$88
  Top 0.406: C39.1 R19.1 arc90 67.5,84.92 R18.2 R20.1
N$89
  Top 0.25: C40.1 88.88,81.38 arc29 88.25,80.62 U$8.17
  Top 0.3: C41.+ 87.75,88.62 arc-90 89.38,87 89.38,84.3 arc90 C40.1
  Top 0.406: R20.2 81.12,86.7 C41.+
N$90  (via drill 0.5)
  Top 0.305: v84.75,87 85.75,83.5 86,81.75 85.75,81 U$8.21
  Bottom 0.305: 84.21,89.49 T1-1T-KK81.P$3 | 84.21,89.49 R28.2 | v84.75,87 84.21,89.49
N$91
  Top 0.25: U$8.18 87.53,79.68 R21.2
N$93
  Top 0.25: U$10.35 116.5,68 arc90 116,68.5 102.5,68.5 arc90 102,68 102,67 arc-90 101.5,66.5 U$1.120
N$94  (1 unrouted)
  Top 0.22: U$1.91 99.75,52 arc90 PAD22.1
  Top 0.25: U$10.43 112.5,66 arc-90 PAD23.1
N$95
  Top 0.22: U$1.119 101,66 | 112,66.5 U$10.44
  Top 0.25: 112,66.5 112,67.5 arc90 111.5,68 103,68 arc90 102.5,67.5 102.5,66.5 arc-90 102,66 101,66
N$96
  Top 0.22: U$1.118 102,65.5 | 111.5,66 U$10.45
  Top 0.25: 111.5,66 111.5,67 arc90 111,67.5 103.5,67.5 arc90 103,67 103,66 arc-90 102.5,65.5 102,65.5
N$97
  Top 0.22: U$1.177 66,74.95 arc90 C55.1
  Top 0.406: C55.1 64.45,77.05 arc90 62.5,79 R33.2 61.92,80 arc90 R34.2
N$98
  Top 0.22: PAD33.1 U$1.4
N$99
  Top 0.22: U$1.57 92.5,32.5 arc-90 PAD34.1
N$100
  Top 0.22: U$1.46 87,33.5 arc-90 PAD35.1
N$101
  Top 0.406: PAD29.1 R34.1
N$102
  Top 0.22: U$1.117 103,65 | 111,65.5 U$10.46
  Top 0.25: 111,65.5 111,66.5 arc90 110.5,67 104,67 arc90 103.5,66.5 103.5,65.5 arc-90 103,65
N$103
  Top 0.22: U$1.88 98.5,50.5 99,50 LED6.1
N$104
  Top 0.406: LED6.2 R39.1
N$105
  Top 0.22: U$1.87 98,50 98.5,49.5 LED5.1
N$106
  Top 0.406: LED5.2 R38.1
N$107
  Top 0.22: U$1.78 LED4.1
N$108
  Top 0.25: U$10.47 110.5,66 arc90 110,66.5 104.5,66.5 arc90 104,66 104,65 arc-90 103.5,64.5 101.5,64.5 arc90 101,64 arc-90 100.5,63.5 U$1.114
N$109
  Top 0.22: U$1.112 101,62.5 106,60.5 U$10.52
N$110
  Top 0.22: U$1.111 100.5,62 105.5,60 U$10.53
N$111
  Top 0.22: U$1.110 100,61.5 105.5,59.5 U$10.54
N$112
  Top 0.22: U$1.109 100,61 105.5,59 U$10.55
N$113
  Top 0.22: U$1.108 100,60.5 105.5,58.5 U$10.56
N$114
  Top 0.22: U$10.60 103,56.5 100,58 U$1.103
N$115
  Top 0.22: U$1.100 101.5,56.5 102,56 U$10.61
N$116
  Top 0.22: U$10.31 120.5,61.5 arc90 121,62 121,65 arc169 R22.2
N$117  (via drill 0.5)
  Top 0.305: v84.75,82.25 85,80.5 U$8.22
  Bottom 0.305: 84.51,85.57 T1-1T-KK81.P$1 | 84.51,85.57 R28.1 | v84.75,82.25 84.51,85.57
N$118
  Top 0.22: U$1.99 101,56 101.5,55.5 U$10.62
N$119
  Top 0.406: ADT4-6T.P$3 U$22.1
N$120  (via drill 0.5)
  Top 0.25: U$11.3 130.68,58.23 arc90 v130.1,58.8
  Top 0.406: v130,67 C36.1 L4.1 C52.+
  Bottom 0.406: v130,67 128,67 arc90 127.5,66.5 127.5,61.5 v130.1,58.8 C53.1
N$121
  Top 0.406: U$7.P$1 C35.1 110.98,91.6 R29.1 110.98,87.94 arc90 R30.1
N$122
  Bottom 0.406: U$20.1 T1-1T-KK81.P$4
N$123  (via drill 0.5)
  Top 0.25: U$11.2 131.3,58.2 131.3,59.2 arc90 130.5,60 129.3,60 arc90 129.1,59.8 129.1,58.5 arc-90 v128.6,58 | U$10.17 119.4,53.6 v119.9,53
  Top 0.406: v119.9,53 C54.1
  Bottom 0.406: v119.9,53 v128.6,58
N$124
  Top 0.406: LED4.2 R37.1
N$125
  Top 0.406: LED3.2 R36.1
N$126
  Top 0.22: U$1.98 100.5,55.5 101,55 U$10.63
N$127
  Top 0.22: U$10.64 98.75,54.5 97.75,54 U$1.95
N$128
  Top 0.22: U$1.76 100.5,44.5 arc-69 LED3.1
N$129
  Top 0.22: U$10.30 121,61 arc90 121.5,61.5 C38.1
N$130
  Top 0.22: U$1.73 99.5,43 arc-90 100,42.5 100,41.5 arc90 100.5,41 LED2.1
N$131
  Top 0.22: U$10.29 121.5,60.5 C37.1
N$132
  Top 0.22: U$10.11 115,51 arc66 C46.1
N$133
  Top 0.22: U$10.10 114.5,49.5 arc-169 C45.1
N$134
  Top 0.22: U$10.19 120.5,55.5 121,54.5 C47.2
  Top 0.406: C49.1 125,53.5 R24.2 C47.2
N$135
  Top 0.25: R25.2 131.97,61.5 U$11.1
  Top 0.406: C50.2 R25.2 R27.1
N$136
  Top 0.25: U$11.4 127,57 R23.1 127.5,60 R25.1
  Top 0.406: R25.1 C50.1
N$137
  Top 0.22: U$10.20 120.5,56 C47.1
  Top 0.406: C47.1 R23.2 C48.1
N$138
  Top 0.25: R26.1 131.97,50.5 U$11.8
  Top 0.406: R31.2 C51.1 R26.1
N$139
  Top 0.25: R26.2 130.03,50.5 U$11.5 126.95,52.95 R24.1
  Top 0.406: C51.2 R26.2
N$140
  Top 0.406: R31.1 136,48 136,52.5 136.96,52.5 ADT4-6T.P$6
N$141
  Top 0.406: R27.2 136,61.5 136,57.5 136.96,57.5 ADT4-6T.P$4
N$142
  Top 0.406: LED2.2 R35.1
N$143
  Top 0.22: U$1.72 99,42.5 arc-90 99.5,42 99.5,39.5 arc90 100,39 LED1.1
N$144
  Top 0.406: LED1.2 R32.1
N$145
  Top 0.22: U$1.71 98.5,42 arc-90 99,41.5 99,39 arc90 99.5,38.5 arc-63 LED7.1
N$146
  Top 0.406: LED7.2 R40.1
N$147
  Top 0.22: U$1.70 98,41.5 arc-90 98.5,41 98.5,38.5 arc53 99,37.5 arc-7 LED8.1
N$148
  Top 0.406: LED8.2 R41.1
VCCD_PLL  (3 unrouted)
  Top 0.22: U$1.60 C32.1 | U$1.1 60.65,35 arc-90 C31.1 | U$1.121 96,68.5 arc90 PAD13.1 PAD12.1 | L1.1 64.5,69 64.5,68.75 U$1.180
  Top 0.3: C32.1 97.05,33.95 arc90 99,32 101,32 arc-90 PAD9.1 PAD8.1 | C31.1 60.49,35.51 arc90 59,37 PAD6.1 PAD7.1 | 64.5,68.75 C34.1
  Top 0.406: L1.1 PAD11.1 PAD10.1 C66.+
  Bottom 0.406: PAD12.1 C33.1

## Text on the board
Top: N2ADR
